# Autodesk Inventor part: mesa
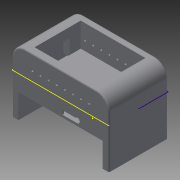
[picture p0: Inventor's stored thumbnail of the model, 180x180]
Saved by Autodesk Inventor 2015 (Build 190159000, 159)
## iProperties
Created: 2016-05
Part Number: mesa
Material: Genérico
Document SubType Name: Modeling
Designer: ALEX
Density: 1 g/cm^3
Appearance: Valor por defecto
Author: ALEX
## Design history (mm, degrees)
sketch "Boceto1"
  geometry: L1 (500, -325)-(-500, -325); L2 (-500, -325)-(-500, 325); L3 (-500, 325)-(500, 325); L4 (500, 325)-(500, -325); L5 (500, -325)-(-500, 325); L6 (-500, -325)-(500, 325); 1 further point
  constraints: 12 end point, 2 midpoint, 2 parallel, 1 horizontal, 1 perpendicular
  dimensions: "d0" = 1000 distance of L2.end L3.end; "d1" = 650 distance of L1.end L2.end
extrude "Extrusión1" new body sketch "Boceto1" distance "d2" = 10; taper "d3" = 0 deg
sketch "Boceto2"
  geometry: L1 (500, -325)-(500, 325) reference; L2 (-500, 325)-(500, 325); L3 (500, 325)-(500, 285); L4 (710, 460)-(-710, 460); L5 (-500, 285)-(-500, 325); L6 (500, 325)-(-500, 325) reference; L7 (500, -325)-(960, -325); L8 (710, -460)-(710, 460); L9 (460, 325)-(500, 325); L10 (500, 325)-(500, -325); L11 (-500, -325)-(500, -325); L12 (500, -325)-(500, -285); L13 (710, -460)-(-710, -460); L14 (-500, -635)-(-500, -325); L15 (-500, -325)-(500, -325) reference; L16 (-500, 325)-(-960, 325); L17 (-710, 460)-(-710, -460); L18 (-460, -325)-(-500, -325); L19 (-500, -325)-(-500, 325); 1 further point
  constraints: 32 end point, 8 parallel, 5 point on line, 4 horizontal, 4 perpendicular
  dimensions: "d4" = 40 distance of L2.end L3.end; "d5" = 40 distance of L9.start L9.end; "d6" = 40 distance of L12.end L11.end; "d7" = 40 distance of L18.start L18.end
extrude "Extrusión2" join sketch "Boceto2" distance "d8" = 150; taper "d9" = 0 deg
node "Boceto3"
sketch "Boceto4"
  geometry: L1 (500, -325)-(500, 325) reference; L2 (-500, 325)-(500, 325); L3 (500, 325)-(500, 285); L4 (400, 285)-(-400, 285); L5 (-500, 285)-(-500, 325); L6 (-500, -325)-(500, -325) reference; L7 (-500, 325)-(-400, 325); L8 (-400, 285)-(-400, -285); L9 (-400, -325)-(-500, -325); L10 (-500, -325)-(-500, 325); L11 (-500, -325)-(500, -325); L12 (500, -325)-(500, -285); L13 (400, -285)-(-400, -285); L14 (-500, -285)-(-500, -325); L15 (500, -325)-(400, -325); L16 (400, -285)-(400, 285); L17 (400, 325)-(500, 325); L18 (500, 325)-(500, -325); 1 further point
  constraints: 32 end point, 8 parallel, 4 horizontal, 4 perpendicular, 4 point on line
  dimensions: "d10" = 40 distance of L2.end L3.end; "d11" = 100 distance of L9.start L9.end; "d12" = 40 distance of L12.end L11.end; "d13" = 100 distance of L17.start L17.end
extrude "Extrusión3" join sketch "Boceto4" distance "d14" = 150; taper "d15" = 0 deg
sketch "Boceto5" dims "d17" = 30
  geometry: L1 (900, 10)-(100, 10) reference; L2 (277.764, 10)-(277.764, 160); L3 (0, 160)-(1000, 160) reference; L4 (277.764, 25)-(232.04, 25); L5 (232.04, 25)-(232.04, 68); L6 (232.04, 68)-(900, 68); L7 (900, 10)-(900, 160) reference; L8 (100, 68)-(232.04, 68); L9 (100, 68)-(125, 68); L10 (125, 68)-(125, 101.198); L11 (900, 68)-(875, 68); L12 (875, 68)-(875, 134.137); C1 r 7.5 at (125, 68); 2 further points
  constraints: 18 end point, 7 point on line, 4 perpendicular, 2 horizontal, 2 vertical, 1 centre point, 1 coincident, 1 collinear, 1 horizontal alignment, 2 other
  dimensions: "d16" = 150 distance of L2.start L2.end (derived); "d18" = 43 distance of L4.end L5.end; "d19" = 25 distance of L8.start L9.end; "d20" = 25 distance of L6.end L11.end; "d21" = 15 diameter of C1
extrude "Extrusión4" cut sketch "Boceto5" distance "d22" = 2000; taper "d23" = 0 deg
sketch "Boceto6"
  geometry: L1 (-500, 325)-(-500, -325) reference; L2 (-500, 0)-(0, 0); L3 (0, 0)-(0, -325); L4 (0, -325)-(513.236, -325); L5 (501.598, -325)-(501.598, 325); L6 (501.598, 325)-(-500, 325)
  constraints: 10 end point, 3 perpendicular, 1 horizontal, 1 midpoint, 1 point on line, 1 vertical
extrude "Extrusión5" cut sketch "Boceto6" distance "d24" = 2000; taper "d25" = 0 deg
sketch "Boceto7"
  geometry: L1 (500, 0)-(500, 160) reference; L2 (125, 68)-(175, 68); L3 (175, 68)-(175, 107.49); L4 (175, 68)-(225, 68); L5 (225, 68)-(225, 115.049); L6 (225, 68)-(275, 68); L7 (275, 68)-(275, 115.049); L8 (275, 68)-(325, 68); L9 (325, 68)-(325, 115.049); L10 (325, 68)-(375, 68); L11 (375, 68)-(375, 115.049); L12 (375, 68)-(425, 68); L13 (425, 68)-(425, 107.49); L14 (425, 68)-(475, 68); L15 (475, 68)-(475, 101.82); C1 r 7.5 at (125, 68) reference; C2 r 7.5 at (175, 68); C3 r 7.5 at (225, 68); C4 r 7.5 at (275, 68); C5 r 7.5 at (325, 68); C6 r 7.5 at (375, 68); C7 r 7.5 at (425, 68); C8 r 7.5 at (475, 68)
  constraints: 28 end point, 7 centre point, 7 coincident, 7 perpendicular, 6 point on line, 1 horizontal
  dimensions: "d27" = 50 distance of L2.start L2.end; "d28" = 50 distance of L2.end L4.end; "d29" = 50 distance of L4.end L6.end; "d30" = 50 distance of L6.end L8.end; "d31" = 50 distance of L8.end L10.end; "d32" = 50 distance of L10.end L12.end; "d33" = 50 distance of L12.end L14.end; "d34" = 15 diameter of C2; "d35" = 15 diameter of C3; "d36" = 15 diameter of C4; "d37" = 15 diameter of C5; "d38" = 15 diameter of C6; "d39" = 15 diameter of C7; "d40" = 15 diameter of C8
extrude "Extrusión6" cut sketch "Boceto7" distance "d41" = 2000; taper "d42" = 0 deg
sketch "Boceto8"
  geometry: L1 (0, 0)-(0, 40); L2 (0, 40)-(150, 40); L3 (150, 40)-(0, 40) reference; L4 (150, 40)-(150, 325); L5 (150, 325)-(160, 325); L6 (160, 325)-(160, 0); L7 (160, 325)-(160, 0) reference; L8 (160, 0)-(0, 0)
  constraints: 12 end point, 3 perpendicular, 2 collinear, 1 vertical
extrude "Extrusión7" join sketch "Boceto8" distance "d43" = 100; taper "d44" = 0 deg
sketch "Boceto9"
  geometry: L1 (-400, -285)-(100, -285) reference; L2 (100, 0)-(0, 0); L3 (0, 0)-(0, -285); L4 (0, -285)-(100, -285); L5 (100, -285)-(100, 0); 1 further point
  constraints: 8 end point, 2 parallel, 1 horizontal, 1 perpendicular, 1 point on line
  dimensions: "d45" = 100 distance of L4.end L3.end
extrude "Extrusión8" join sketch "Boceto9" distance "d46" = 150; taper "d47" = 0 deg
sketch "Boceto10"
  geometry: L1 (600, 160)-(0, 160); L2 (0, 160)-(0, 0); L3 (0, 0)-(600, 0); L4 (600, 0)-(600, 160); 1 further point
  constraints: 8 end point, 2 parallel, 1 horizontal, 1 perpendicular
extrude "Extrusión9" join sketch "Boceto10" distance "d48" = 40; taper "d49" = 0 deg
sketch "Boceto11"
  geometry: L1 (-500, -325)-(100, -325) reference; L2 (-500, 40)-(-500, -325) reference; L3 (100, 40)-(-500, 40); L4 (-500, 40)-(-500, -142.5); L5 (-500, -142.5)-(100, -142.5); L6 (100, -142.5)-(100, 40); 1 further point
  constraints: 8 end point, 2 parallel, 1 horizontal, 1 midpoint, 1 perpendicular
sketch "Boceto12"
  geometry: C1 r 7.5 at (125, 92) reference; C2 r 7.5 at (125, 92); C3 r 7.5 at (175, 92) reference; C4 r 7.5 at (175, 92); C5 r 7.5 at (225, 92) reference; C6 r 7.5 at (225, 92); C7 r 7.5 at (275, 92) reference; C8 r 7.5 at (275, 92); C9 r 7.5 at (325, 92) reference; C10 r 7.5 at (325, 92); C11 r 7.5 at (375, 92) reference; C12 r 7.5 at (375, 92); C13 r 7.5 at (425, 92) reference; C14 r 7.5 at (425, 92); C15 r 7.5 at (475, 92) reference; C16 r 7.5 at (475, 92); 1 further point
  constraints: 8 centre point, 8 coincident
extrude "Extrusión10" cut sketch "Boceto12" distance "d51" = 500; taper "d52" = 0 deg
fillet "Empalme1" dims "d53" = 80
fillet "Empalme2" dims "d54" = 80
fillet "Empalme3" dims "d55" = 10
fillet "Empalme4" dims "d56" = 10
sketch "Boceto13"
  geometry: 1 further point
sketch "Boceto14"
  geometry: L1 (500, 30)-(500, -315) reference; L2 (-100, -315)-(-100, 30) reference; L3 (-90, 30)-(490, 30); L4 (490, 30)-(490, -315); L5 (490, -315)-(-90, -315); L6 (-90, -315)-(-90, 30); L7 (-100, 30)-(-100, -315); L8 (-100, -315)-(-100, 30) reference; L9 (-90, -325)-(490, -325); L10 (-90, -325)-(490, -325) reference; L11 (500, -315)-(500, 30); L12 (490, 40)-(-90, 40); A1 r 10 centre (-90, 30) between (-90, 40) and (-100, 30) reference; A2 r 10 centre (490, -315) between (490, -325) and (500, -315) reference; A3 r 10 centre (-90, 30) between (-90, 40) and (-100, 30); A4 r 10 centre (490, 30) between (500, 30) and (490, 40); A5 r 10 centre (490, -315) between (490, -325) and (500, -315); A6 r 10 centre (-90, -315) between (-100, -315) and (-90, -325); A7 r 10 centre (-90, -315) between (-100, -315) and (-90, -325) reference; 1 further point
  constraints: 16 end point, 9 point on circle, 6 tangent, 4 centre point, 4 equal length, 3 perpendicular, 2 concentric, 1 horizontal
sketch "Boceto15"
  geometry: 1 further point
sketch "Boceto16"
  geometry: 1 further point
sketch "Boceto17"
  geometry: L1 (380, -67.5)-(460, -217.5); L2 (460, -67.5)-(380, -217.5); L3 (0, -217.5)-(-40, -217.5); L4 (-40, -217.5)-(-40, -67.5); L5 (-40, -67.5)-(0, -67.5); L6 (40, -217.5)-(-40, -67.5); L7 (-40, -217.5)-(40, -67.5); L8 (0, -67.5)-(0, -217.5); L9 (0, -285)-(0, 0) reference; L10 (440, -217.5)-(440, -67.5); L11 (360, -67.5)-(360, -217.5); L12 (400, 0)-(400, -285) reference; L13 (360, -217.5)-(440, -67.5); L14 (440, -217.5)-(360, -67.5); L15 (400, -67.5)-(400, -217.5); L16 (440, -67.5)-(400, -67.5); L17 (380, -67.5)-(360, -67.5); L18 (360, -217.5)-(380, -217.5); L19 (400, -217.5)-(440, -217.5); 3 further points
  constraints: 34 end point, 7 midpoint, 6 parallel, 4 point on line, 3 horizontal, 3 perpendicular
  dimensions: "d57" = 80 distance of L1.end L2.end; "d58" = 150 distance of L2.start L1.end; "d59" = 80 distance of L4.end L7.end; "d60" = 80 distance of L11.start L10.end
extrude "Extrusión11" cut sketch "Boceto17" distance "d61" = 100; taper "d62" = 0 deg
node "Boceto18"
extrude "Extrusión12" join sketch "Boceto14" distance "d63" = 75; taper "d64" = 0 deg
sketch "Boceto19"
  geometry: L1 (-100, 40)-(500, 40); L2 (500, 40)-(500, -325); L3 (500, -325)-(-100, -325); L4 (-100, -325)-(-100, 40); 1 further point
  constraints: 8 end point, 2 parallel, 1 horizontal, 1 perpendicular
extrude "Extrusión13" join sketch "Boceto19" distance "d65" = 15; taper "d66" = 0 deg
sketch "Boceto20"
  geometry: 1 further point
fillet "Empalme5" dims "d67" = 10
fillet "Empalme6" dims "d68" = 10
fillet "Empalme7" dims "d69" = 9.9
fillet "Empalme8" dims "d70" = 9.9
sketch "Boceto21"
  geometry: L1 (490.1, 40)-(-90, 40) reference; L2 (500, -325)-(480, -325); L3 (480, 40)-(500, 40); L4 (500, 40)-(500, -325); L5 (490, -325)-(-90.017, -325) reference; L6 (-100, 40)-(-60, 40); L7 (-60, 40)-(-60, -325); L8 (-60, -325)-(-100, -325); L9 (-100, -325)-(-100, 40); L10 (500, -325)-(460, -325); L11 (460, -325)-(460, 40); L12 (460, 40)-(500, 40); L13 (500, 40)-(500, -325); 1 further point
  constraints: 22 end point, 5 parallel, 4 point on line, 3 horizontal, 2 perpendicular
  dimensions: "d71" = 20 distance of L3.start L3.end; "d72" = 40 distance of L7.end L8.end; "d73" = 40 distance of L11.end L12.end
extrude "Extrusión14" join sketch "Boceto21" distance "d74" = 150; taper "d75" = 0 deg
fillet "Empalme9" dims "d76" = 9.9
fillet "Empalme10" dims "d77" = 9.9
fillet "Empalme11" dims "d78" = 9.98
fillet "Empalme12" dims "d79" = 9.9
sketch "Boceto22"
  geometry: L1 (311.479, 235)-(219.848, 235); L2 (311.479, 210.624)-(311.479, 235); L3 (590, 235)-(10, 235) reference; L4 (311.479, 210.624)-(231.557, 210.624); A1 r 15 centre (219.848, 220) between (219.848, 235) and (231.557, 210.624); 1 further point
  constraints: 6 end point, 2 perpendicular, 2 point on circle, 1 centre point, 1 horizontal, 1 point on line
extrude "Extrusión15" cut sketch "Boceto22" distance "d83" = 150; taper "d84" = 0 deg
sketch "Boceto23"
  geometry: L1 (323.931, -225)-(231.479, -225); L2 (231.479, -225)-(231.479, -200.624); L3 (231.479, -200.624)-(312.223, -200.624); A1 r 15 centre (323.931, -210) between (323.931, -225) and (312.223, -200.624); 1 further point
  constraints: 6 end point, 2 perpendicular, 2 point on circle, 1 centre point
extrude "Extrusión16" cut sketch "Boceto23" distance "d87" = 150; taper "d88" = 0 deg
node "Sólido1"
feature "耀쀿"
